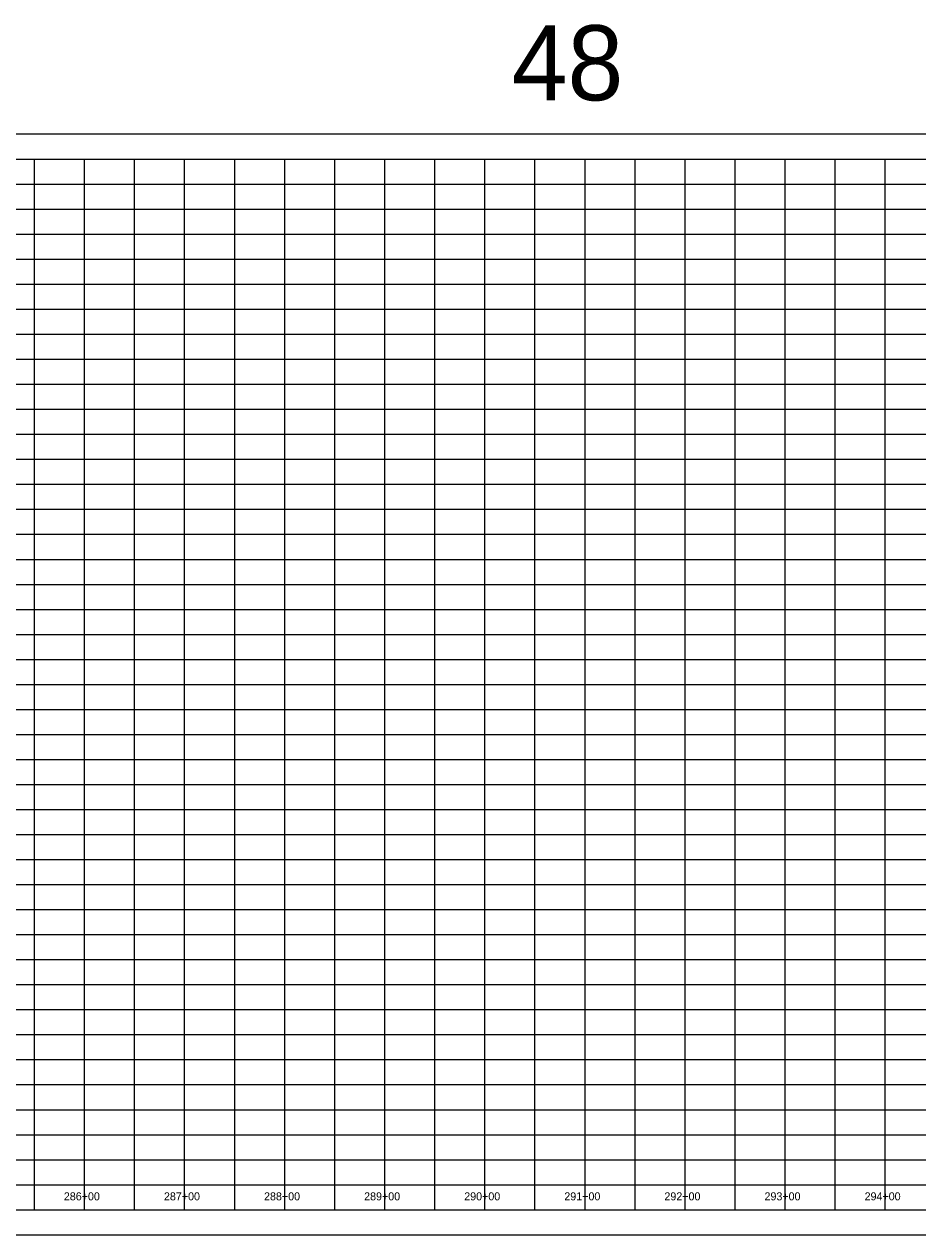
# Model space of a CAD drawing. Extents: x 1873632 to 1926512, y 813126 to 836257.
# Drawn here: x 1906903 to 1907795, y 830505 to 831714 of the extents above; entities that cross this region are included whole.
import ezdxf

# ---------------------------------------------------------------- set-up
doc = ezdxf.new("R2010")
doc.units = 0
for name, color, linetype in [('RD_DDB_StaTX', 7, 'Continuous'), ('RD_PD_WallFill', 7, 'Continuous'), ('RD_SHT_IplotShp', 7, 'Continuous')]:
    doc.layers.add(name, color=color, linetype=linetype)

msp = doc.modelspace()

# ---------------------------------------------------------------- linework, layer by layer
at = {"layer": 'RD_PD_WallFill'}
for p, q in [((1905062.9, 831579.6), (1910412.9, 831579.6)), ((1906912.9, 830529.6), (1906912.9, 831579.6)), ((1906912.9, 830529.6), (1906912.9, 831579.6)), ((1906962.9, 830529.6), (1906962.9, 831579.6)), ((1906962.9, 830529.6), (1906962.9, 831579.6)), ((1907012.9, 830529.6), (1907012.9, 831579.6)), ((1907012.9, 830529.6), (1907012.9, 831579.6)), ((1907062.9, 830529.6), (1907062.9, 831579.6)), ((1907062.9, 830529.6), (1907062.9, 831579.6)), ((1907112.9, 830529.6), (1907112.9, 831579.6)), ((1907112.9, 830529.6), (1907112.9, 831579.6)), ((1907162.9, 830529.6), (1907162.9, 831579.6)), ((1907162.9, 830529.6), (1907162.9, 831579.6)), ((1907212.9, 830529.6), (1907212.9, 831579.6)), ((1907212.9, 830529.6), (1907212.9, 831579.6)), ((1907262.9, 830529.6), (1907262.9, 831579.6)), ((1907262.9, 830529.6), (1907262.9, 831579.6)), ((1907312.9, 830529.6), (1907312.9, 831579.6)), ((1907312.9, 830529.6), (1907312.9, 831579.6)), ((1907362.9, 830529.6), (1907362.9, 831579.6)), ((1907362.9, 830529.6), (1907362.9, 831579.6)), ((1907412.9, 830529.6), (1907412.9, 831579.6)), ((1907412.9, 830529.6), (1907412.9, 831579.6)), ((1907462.9, 830529.6), (1907462.9, 831579.6)), ((1907462.9, 830529.6), (1907462.9, 831579.6)), ((1907512.9, 830529.6), (1907512.9, 831579.6)), ((1907512.9, 830529.6), (1907512.9, 831579.6)), ((1907562.9, 830529.6), (1907562.9, 831579.6)), ((1907562.9, 830529.6), (1907562.9, 831579.6)), ((1907612.9, 830529.6), (1907612.9, 831579.6)), ((1907612.9, 830529.6), (1907612.9, 831579.6)), ((1907662.9, 830529.6), (1907662.9, 831579.6)), ((1907662.9, 830529.6), (1907662.9, 831579.6)), ((1907712.9, 830529.6), (1907712.9, 831579.6)), ((1907712.9, 830529.6), (1907712.9, 831579.6)), ((1907762.9, 830529.6), (1907762.9, 831579.6)), ((1907762.9, 830529.6), (1907762.9, 831579.6)), ((1905512.9, 831554.6), (1910412.9, 831554.6)), ((1905512.9, 831554.6), (1910412.9, 831554.6)), ((1905512.9, 831529.6), (1910412.9, 831529.6)), ((1905512.9, 831504.6), (1910412.9, 831504.6)), ((1905512.9, 831479.6), (1910412.9, 831479.6)), ((1905512.9, 831454.6), (1910412.9, 831454.6)), ((1905062.9, 831429.6), (1910412.9, 831429.6)), ((1905062.9, 831404.6), (1910412.9, 831404.6)), ((1905062.9, 831379.6), (1910412.9, 831379.6)), ((1905062.9, 831354.6), (1910412.9, 831354.6)), ((1905062.9, 831329.6), (1910412.9, 831329.6)), ((1905062.9, 831304.6), (1910412.9, 831304.6)), ((1905062.9, 831279.6), (1910412.9, 831279.6)), ((1905062.9, 831254.6), (1910412.9, 831254.6)), ((1905062.9, 831229.6), (1910412.9, 831229.6)), ((1905062.9, 831204.6), (1910412.9, 831204.6)), ((1905062.9, 831179.6), (1910412.9, 831179.6)), ((1905062.9, 831154.6), (1910412.9, 831154.6)), ((1905062.9, 831129.6), (1910412.9, 831129.6)), ((1905062.9, 831104.6), (1910412.9, 831104.6)), ((1905062.9, 831079.6), (1910412.9, 831079.6)), ((1905062.9, 831054.6), (1910412.9, 831054.6)), ((1905062.9, 831029.6), (1910412.9, 831029.6)), ((1905062.9, 831004.6), (1910412.9, 831004.6)), ((1905062.9, 830979.6), (1910412.9, 830979.6)), ((1905062.9, 830954.6), (1910412.9, 830954.6)), ((1905062.9, 830929.6), (1910412.9, 830929.6)), ((1905062.9, 830904.6), (1910412.9, 830904.6)), ((1905062.9, 830879.6), (1910412.9, 830879.6)), ((1905062.9, 830854.6), (1910412.9, 830854.6)), ((1905062.9, 830829.6), (1910412.9, 830829.6)), ((1905062.9, 830804.6), (1910412.9, 830804.6)), ((1905062.9, 830779.6), (1910412.9, 830779.6)), ((1905062.9, 830754.6), (1910412.9, 830754.6)), ((1905062.9, 830729.6), (1910412.9, 830729.6)), ((1905062.9, 830704.6), (1910412.9, 830704.6)), ((1905062.9, 830679.6), (1910412.9, 830679.6)), ((1905062.9, 830654.6), (1910412.9, 830654.6)), ((1905062.9, 830629.6), (1910412.9, 830629.6)), ((1905062.9, 830604.6), (1910412.9, 830604.6)), ((1905062.9, 830579.6), (1910412.9, 830579.6)), ((1905062.9, 830554.6), (1910412.9, 830554.6)), ((1905062.9, 830529.6), (1910412.9, 830529.6)), ((1905062.9, 830529.6), (1910412.9, 830529.6))]:
    msp.add_line(p, q, dxfattribs=at)
at = {"layer": 'RD_SHT_IplotShp'}
msp.add_lwpolyline([(1905037.9, 830504.6), (1910437.9, 830504.6), (1910437.9, 831604.6), (1905037.9, 831604.6)], close=True, dxfattribs=at)

# ---------------------------------------------------------------- texts
at = {"layer": 'RD_DDB_StaTX'}
for s, p in [('286+00', (1906942.2, 830539)), ('287+00', (1907042.2, 830539)), ('288+00', (1907142.2, 830539)), ('289+00', (1907242.2, 830539)), ('290+00', (1907342.2, 830539)), ('291+00', (1907442.2, 830539)), ('292+00', (1907542.2, 830539)), ('293+00', (1907642.2, 830539)), ('294+00', (1907742.2, 830539))]:
    msp.add_text(s, height=8, dxfattribs=at).set_placement(p)
at = {"layer": 'RD_PD_WallFill'}
msp.add_text('48', height=75, dxfattribs=at).set_placement((1907389.6, 831638.3))
msp.add_text('48', height=75, dxfattribs=at).set_placement((1907389.6, 831638.3))

doc.saveas('drawing.dxf')
